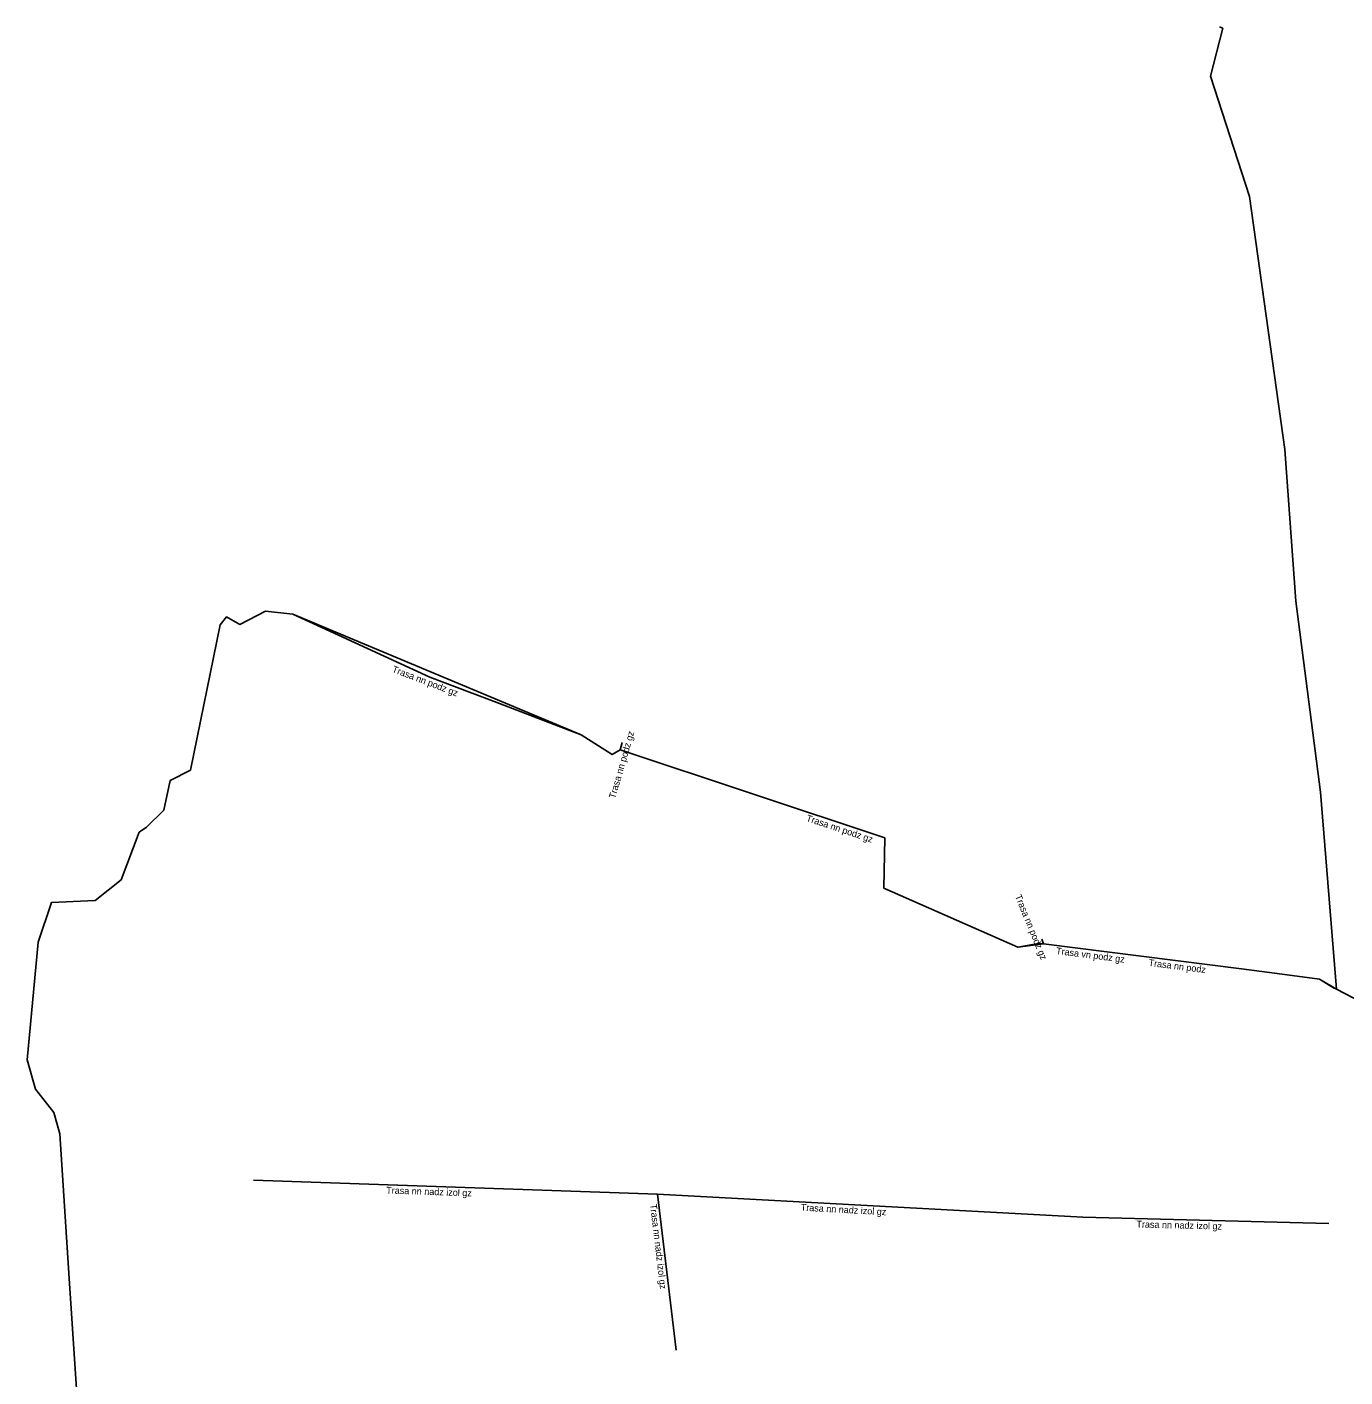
# Model space of a CAD drawing. Extents: x -778200 to -777730, y -1024936 to -1024518.
# Drawn here: x -778200.5 to -778102.6, y -1024726 to -1024625.8 of the extents above; entities that cross this region are included whole.
import ezdxf

# ---------------------------------------------------------------- set-up
doc = ezdxf.new("R2010")
doc.units = 0
for name, color, linetype in [('Popiskový text - Ostatní atributy Trasy', 7, 'Continuous'), ('Spojnice NN', 7, 'Continuous'), ('Spojnice VN', 7, 'Continuous')]:
    doc.layers.add(name, color=color, linetype=linetype)

msp = doc.modelspace()

# ---------------------------------------------------------------- linework, layer by layer
at = {"layer": 'Spojnice NN'}
for points in [[(-778182.76, -1024669.13), (-778180.72, -1024669.35), (-778170.55, -1024674.02), (-778165.39, -1024675.99), (-778162.48, -1024677.1), (-778159.31, -1024678.31), (-778157.01, -1024679.77), (-778156.43, -1024679.43)], [(-778156.43, -1024679.43), (-778156.27, -1024678.89)], [(-778156.43, -1024679.43), (-778136.78, -1024685.96), (-778136.85, -1024689.7), (-778126.9, -1024694.08), (-778125.52, -1024693.82), (-778124.99, -1024693.82)], [(-778124.99, -1024693.82), (-778125.12, -1024693.49)], [(-778124.99, -1024693.82), (-778110.3, -1024695.69), (-778107.28, -1024696.08), (-778104.51, -1024696.44), (-778103.25, -1024697.2)], [(-778103.25, -1024697.2), (-778099.64, -1024699.07), (-778094.75, -1024699.61), (-778094.01, -1024699.6)], [(-778183.64, -1024711.38), (-778153.65, -1024712.4)], [(-778153.65, -1024712.4), (-778152.27, -1024723.98)], [(-778153.65, -1024712.4), (-778122.09, -1024714.13)], [(-778122.09, -1024714.13), (-778103.83, -1024714.59)]]:
    msp.add_lwpolyline(points, dxfattribs=at)
at = {"layer": 'Spojnice VN'}
for points in [[(-778190.3, -1024683.91), (-778189.83, -1024681.7), (-778188.32, -1024680.93), (-778186.12, -1024670.15), (-778185.65, -1024669.56), (-778184.67, -1024670.12), (-778182.76, -1024669.13), (-778180.72, -1024669.35), (-778159.31, -1024678.31), (-778157.01, -1024679.77), (-778156.43, -1024679.43), (-778136.78, -1024685.96), (-778136.85, -1024689.7), (-778126.9, -1024694.08), (-778124.99, -1024693.82), (-778110.3, -1024695.69), (-778107.28, -1024696.08), (-778104.51, -1024696.44), (-778103.47, -1024697.09), (-778103.25, -1024697.2), (-778104.44, -1024682.57), (-778106.28, -1024668.39), (-778107.09, -1024657.13), (-778109.72, -1024638.34), (-778112.61, -1024629.41), (-778111.7, -1024625.86), (-778111.93, -1024625.76)], [(-778190.3, -1024683.91), (-778191.6, -1024685.16), (-778192.13, -1024685.54), (-778193.48, -1024689.07), (-778195.4, -1024690.62), (-778198.65, -1024690.76), (-778199.63, -1024693.7), (-778200.46, -1024702.45), (-778199.84, -1024704.62), (-778198.48, -1024706.35), (-778198.03, -1024707.93), (-778197.33, -1024718.68), (-778196.42, -1024732.46)]]:
    msp.add_lwpolyline(points, dxfattribs=at)

# ---------------------------------------------------------------- texts
at = {"layer": 'Popiskový text - Ostatní atributy Trasy'}
for s, rotation, p in [('Trasa nn podz gz', 339.1234, (-778173.4, -1024673.63)), ('Trasa nn podz gz', 73.943, (-778156.8, -1024683.08)), ('Trasa nn podz gz', 341.6132, (-778142.66, -1024684.7)), ('Trasa nn podz gz', 292.2831, (-778127.13, -1024690.29)), ('Trasa vn podz gz', 352.7094, (-778124.09, -1024694.58)), ('Trasa nn podz', 352.7094, (-778117.22, -1024695.46)), ('Trasa nn nadz izol gz', 358.052, (-778173.8, -1024712.36)), ('Trasa nn nadz izol gz', 276.7718, (-778154.21, -1024713.17)), ('Trasa nn nadz izol gz', 356.8583, (-778143.03, -1024713.63)), ('Trasa nn nadz izol gz', 358.5475, (-778118.11, -1024714.88))]:
    msp.add_text(s, height=0.5, rotation=rotation, dxfattribs=at).set_placement(p)

doc.saveas('drawing.dxf')
